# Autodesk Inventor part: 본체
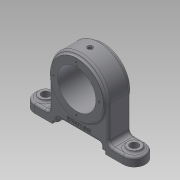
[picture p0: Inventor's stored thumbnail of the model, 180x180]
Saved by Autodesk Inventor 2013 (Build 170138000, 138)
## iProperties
Created: 2019-05
Part Number: 본체
Material: 일반
Document SubType Name: Modeling
Designer: Administrator
Density: 1 g/cm^3
Author: Administrator
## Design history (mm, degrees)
sketch "스케치1"
  geometry: L1 (-40, 0)-(40, 0); L2 (40, 0)-(40, -48); L3 (40, -48)-(75, -48); L4 (75, -48)-(75, -60); L5 (75, -60)-(36, -60); L6 (36, -60)-(36, -56); L7 (36, -56)-(30, -56); L8 (30, -56)-(30, -50); L9 (30, -50)-(-30, -50); L10 (-30, -50)-(-30, -56); L11 (-30, -56)-(-36, -56); L12 (-36, -56)-(-36, -60); L13 (-36, -60)-(-75, -60); L14 (-75, -60)-(-75, -48); L15 (-75, -48)-(-40, -48); L16 (-40, -48)-(-40, 0); A1 r 40 centre (0, 0) between (40, 0) and (-40, 0); 3 further points
  constraints: 32 end point, 11 parallel, 3 perpendicular, 2 coincident, 2 midpoint, 2 point on circle, 1 centre point, 1 collinear, 1 horizontal, 1 horizontal alignment, 1 tangent, 1 vertical alignment
  dimensions: "d5" = 4 distance of L11.end L12.end; "d6" = 4 distance of L5.end L6.end; "d7" = 60 distance between parallel lines of L8 L10; "d8" = 150 distance between parallel lines of L4 L14; "d9" = 60 distance between parallel lines of L13 L1; "d11" = 10 distance between parallel lines of L13 L9; "d12" = 75 distance from line of point (0, 0) L14; "d13" = 12 distance of L13.end L14.end; "d14" = 12 distance of L3.end L4.end; "d15" = 72 distance between parallel lines of L6 L12; "d16" = 80 diameter of A1; "d17" = 39 distance between parallel lines of L12 L14
extrude "돌출1" new body sketch "스케치1" stored distance "d18" = 30; taper "d19" = 0 deg
sketch "스케치3"
  geometry: C1 r 36 at (0, 0); 1 further point
  constraints: 1 centre point, 1 coincident
  dimensions: "d21" = 72 diameter of C1
extrude "돌출2" join sketch "스케치3" stored distance "d22" = 36; taper "d23" = 0 deg
sketch "스케치5"
  geometry: C1 r 36 at (0, 0) reference; C2 r 26 at (0, 0)
  constraints: 1 centre point, 1 coincident
  dimensions: "d24" = 52 diameter of C2
extrude "돌출3" cut sketch "스케치5" stored distance "d25" = 36; taper "d26" = 0 deg
sketch "스케치6"
  geometry: C1 r 9 at (20, 15); 1 further point
  constraints: 1 centre point, 1 horizontal alignment
  dimensions: "d27" = 18 diameter of C1; "d29" = 60 distance of point (-40, 15) C1.centre
extrude "돌출4" join sketch "스케치6" distance "d30" = 3; taper "d31" = 0 deg
sketch "스케치7"
  geometry: C1 r 9 at (0, 0) reference; C2 r 5.5 at (0, 0); 1 further point
  constraints: 1 centre point, 1 coincident
  dimensions: "d32" = 11 diameter of C2
extrude "돌출5" cut sketch "스케치7" stored distance "d33" = 3; taper "d34" = 0 deg
sketch "스케치8" dims "d35" = 62
  geometry: C1 r 26 at (0, 0) reference; C2 r 36 at (0, 0) reference; 2 further points
  constraints: 2 vertical alignment, 1 coincident, 2 other
hole "구멍1" sketch "스케치8" at (0, 31) diameter "d36" = 3.242; stored, may be unused: countersink angle "d40" = 90 deg, drill point angle "d42" = 118 deg; dims "d37" = 6, "d38" = 4, "d39" = 2, "d41" = 8
sketch "스케치9"
  geometry: C1 r 1.5 at (0, 26); 1 further point
  constraints: 2 vertical alignment, 1 centre point, 1 other
  dimensions: "d46" = 3 diameter of C1
extrude "돌출6" cut sketch "스케치9" stored distance "d47" = 3; taper "d48" = 0 deg
node "작업 평면1"
sketch "스케치10"
  geometry: 2 further points
  constraints: 1 coincident
hole "구멍2" sketch "스케치10" at (0, 0) diameter "d49" = 4.917; stored, may be unused: countersink angle "d53" = 90 deg, drill point angle "d55" = 118 deg; dims "d50" = 8, "d51" = 7, "d52" = 1, "d54" = 10
sketch "스케치11"
  geometry: C1 r 1 at (0, 0); 1 further point
  constraints: 1 centre point, 1 coincident
  dimensions: "d56" = 2 diameter of C1
extrude "돌출7" cut sketch "스케치11" distance "d57" = 15.5; taper "d58" = 0 deg
fillet "모깎기1" dims "d59" = 3
fillet "모깎기2" dims "d60" = 15
fillet "모깎기3" dims "d61" = 3
fillet "모깎기4" dims "d62" = 6
fillet "모깎기5" dims "d63" = 3
fillet "모깎기6" dims "d64" = 3
fillet "모깎기7" dims "d65" = 3
node "작업 평면2"
sketch "스케치12"
  geometry: L1 (-27, -50)-(27, -50) reference; 2 further points
  constraints: 1 vertical alignment, 1 other
  dimensions: "d67" = 7 distance from line of L1 point (0, -43)
feature "엠보싱1" sketch "스케치12" dims "d68" = 0.5, "d69" = 0
node "솔리드1"
mirror "대칭2"
pattern_circular "원형 패턴1" dims angle "d44" = 360 deg
mirror "대칭3"
